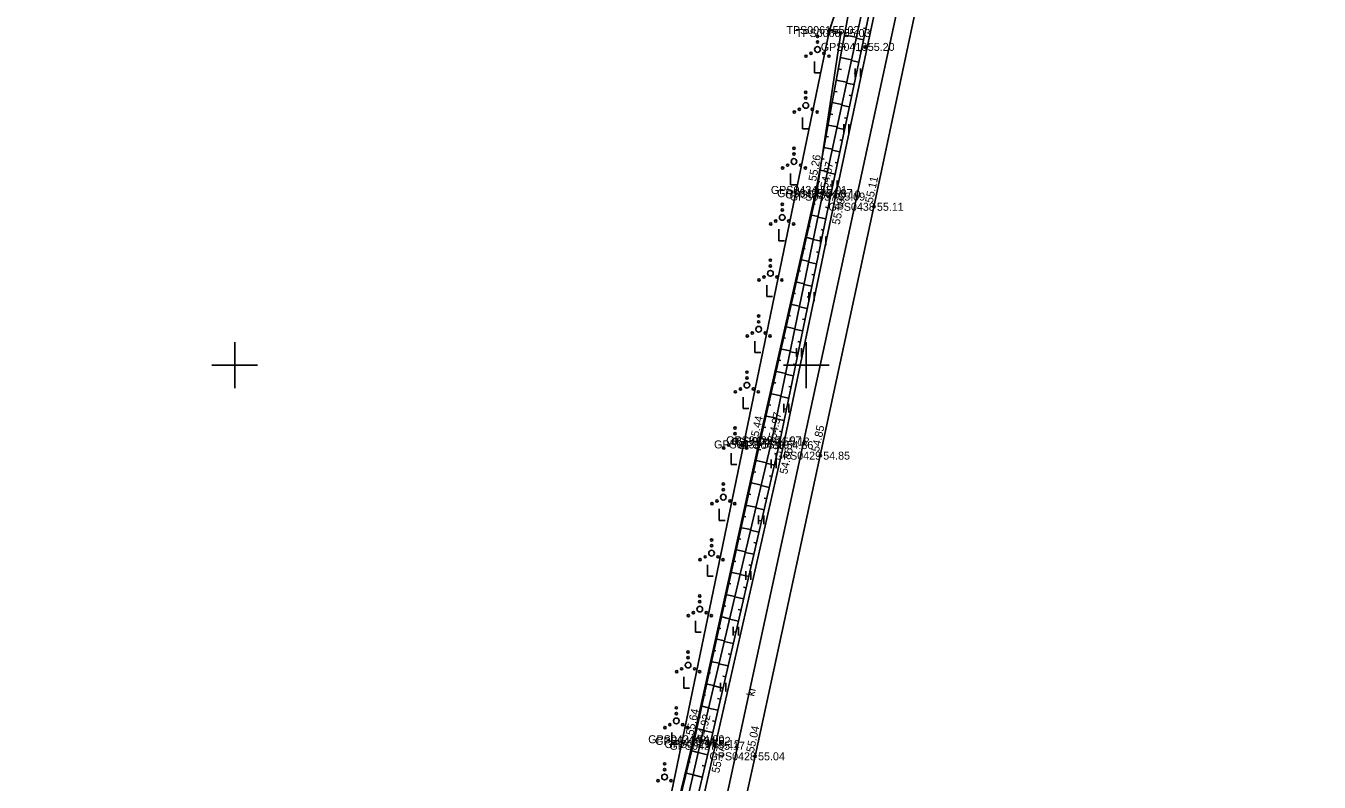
# Model space of a CAD drawing. Extents: x 551623 to 559850, y 6561220 to 6567135.
# Drawn here: x 556681.7 to 556794.9, y 6563363.5 to 6563429.7 of the extents above; entities that cross this region are included whole.
import ezdxf

# ---------------------------------------------------------------- set-up
doc = ezdxf.new("R2010")
doc.units = 0
for name, color, linetype in [('HALJASTUS', 7, 'Continuous'), ('KORGUS-EH2000', 7, 'Continuous'), ('MOOTKORG-EH2000', 7, 'Continuous'), ('MOOTMPUNKT', 7, 'Continuous'), ('MOOTNR', 7, 'Continuous'), ('MOOTPIIR', 7, 'Continuous'), ('PIIR', 7, 'Continuous'), ('RELJEEF', 7, 'Continuous'), ('TEE', 7, 'Continuous'), ('VORK', 7, 'Continuous')]:
    doc.layers.add(name, color=color, linetype=linetype)

msp = doc.modelspace()

# ---------------------------------------------------------------- linework, layer by layer
at = {"layer": 'HALJASTUS'}
for p, q in [((556750.72, 6563426.55), (556750.72, 6563425.55)), ((556750.72, 6563425.55), (556751.22, 6563425.55)), ((556754.29, 6563425.95), (556754.29, 6563425.19)), ((556754.75, 6563425.95), (556754.75, 6563425.19)), ((556749.68, 6563421.66), (556749.68, 6563420.66)), ((556753.28, 6563421.06), (556753.28, 6563420.29)), ((556753.73, 6563421.06), (556753.73, 6563420.29)), ((556749.68, 6563420.66), (556750.18, 6563420.66)), ((556748.64, 6563416.77), (556748.64, 6563415.77)), ((556748.64, 6563415.77), (556749.14, 6563415.77)), ((556752.26, 6563416.16), (556752.26, 6563415.4)), ((556752.72, 6563416.16), (556752.72, 6563415.4)), ((556747.6, 6563411.88), (556747.6, 6563410.88)), ((556747.6, 6563410.88), (556748.1, 6563410.88)), ((556751.25, 6563411.26), (556751.25, 6563410.5)), ((556751.71, 6563411.26), (556751.71, 6563410.5)), ((556746.56, 6563406.99), (556746.56, 6563405.99)), ((556750.24, 6563406.37), (556750.24, 6563405.61)), ((556750.69, 6563406.37), (556750.69, 6563405.61)), ((556746.56, 6563405.99), (556747.06, 6563405.99)), ((556745.52, 6563402.1), (556745.52, 6563401.1)), ((556745.52, 6563401.1), (556746.02, 6563401.1)), ((556749.14, 6563401.49), (556749.14, 6563400.73)), ((556749.59, 6563401.49), (556749.59, 6563400.73)), ((556744.48, 6563397.21), (556744.48, 6563396.21)), ((556744.48, 6563396.21), (556744.98, 6563396.21)), ((556748.03, 6563396.61), (556748.03, 6563395.85)), ((556748.49, 6563396.61), (556748.49, 6563395.85)), ((556743.44, 6563392.32), (556743.44, 6563391.32)), ((556746.93, 6563391.74), (556746.93, 6563390.98)), ((556747.38, 6563391.74), (556747.38, 6563390.98)), ((556743.44, 6563391.32), (556743.94, 6563391.32)), ((556742.4, 6563387.43), (556742.4, 6563386.43)), ((556742.4, 6563386.43), (556742.9, 6563386.43)), ((556745.82, 6563386.86), (556745.82, 6563386.1)), ((556746.28, 6563386.86), (556746.28, 6563386.1)), ((556741.36, 6563382.54), (556741.36, 6563381.54)), ((556741.36, 6563381.54), (556741.86, 6563381.54)), ((556744.72, 6563381.98), (556744.72, 6563381.22)), ((556745.17, 6563381.98), (556745.17, 6563381.22)), ((556740.32, 6563377.65), (556740.32, 6563376.65)), ((556743.62, 6563377.11), (556743.62, 6563376.35)), ((556744.07, 6563377.11), (556744.07, 6563376.35)), ((556740.32, 6563376.65), (556740.82, 6563376.65)), ((556739.28, 6563372.76), (556739.28, 6563371.76)), ((556742.51, 6563372.23), (556742.51, 6563371.47)), ((556742.97, 6563372.23), (556742.97, 6563371.47)), ((556739.28, 6563371.76), (556739.78, 6563371.76)), ((556738.24, 6563367.87), (556738.24, 6563366.87)), ((556738.24, 6563366.87), (556738.74, 6563366.87)), ((556741.41, 6563367.35), (556741.41, 6563366.59)), ((556741.86, 6563367.35), (556741.86, 6563366.59))]:
    msp.add_line(p, q, dxfattribs=at)
msp.add_lwpolyline([(556752.05, 6563429.3), (556753.02, 6563429.04), (556750.97, 6563415.32), (556745.92, 6563393.07), (556740.24, 6563367.29), (556734.99, 6563345.72), (556730.18, 6563321.97), (556724.64, 6563294.5)], dxfattribs=at)
for centre, radius in [((556750.99, 6563428.75), 0.1), ((556750.99, 6563427.6), 0.25), ((556750.99, 6563428.25), 0.1), ((556749.99, 6563427.02), 0.1), ((556750.42, 6563427.27), 0.1), ((556751.55, 6563427.27), 0.1), ((556751.99, 6563427.02), 0.1), ((556749.96, 6563423.86), 0.1), ((556749.96, 6563423.36), 0.1), ((556748.96, 6563422.13), 0.1), ((556749.4, 6563422.38), 0.1), ((556749.96, 6563422.71), 0.25), ((556750.53, 6563422.38), 0.1), ((556750.96, 6563422.13), 0.1), ((556748.93, 6563418.96), 0.1), ((556748.37, 6563417.49), 0.1), ((556748.93, 6563417.81), 0.25), ((556748.93, 6563418.46), 0.1), ((556749.5, 6563417.49), 0.1), ((556747.93, 6563417.24), 0.1), ((556749.93, 6563417.24), 0.1), ((556747.9, 6563414.07), 0.1), ((556747.9, 6563412.92), 0.25), ((556747.9, 6563413.57), 0.1), ((556746.9, 6563412.35), 0.1), ((556747.34, 6563412.6), 0.1), ((556748.47, 6563412.6), 0.1), ((556748.9, 6563412.35), 0.1), ((556746.87, 6563409.18), 0.1), ((556746.87, 6563408.68), 0.1), ((556745.87, 6563407.45), 0.1), ((556746.31, 6563407.7), 0.1), ((556746.87, 6563408.03), 0.25), ((556747.44, 6563407.7), 0.1), ((556747.87, 6563407.45), 0.1), ((556745.84, 6563404.29), 0.1), ((556745.84, 6563403.79), 0.1), ((556745.28, 6563402.81), 0.1), ((556745.84, 6563403.14), 0.25), ((556746.41, 6563402.81), 0.1), ((556744.84, 6563402.56), 0.1), ((556746.84, 6563402.56), 0.1), ((556744.81, 6563399.39), 0.1), ((556744.81, 6563398.24), 0.25), ((556744.81, 6563398.89), 0.1), ((556743.81, 6563397.67), 0.1), ((556744.25, 6563397.92), 0.1), ((556745.38, 6563397.92), 0.1), ((556745.81, 6563397.67), 0.1), ((556743.78, 6563394.5), 0.1), ((556743.78, 6563394), 0.1), ((556742.78, 6563392.77), 0.1), ((556743.22, 6563393.02), 0.1), ((556743.78, 6563393.35), 0.25), ((556744.35, 6563393.02), 0.1), ((556744.78, 6563392.77), 0.1), ((556742.75, 6563389.61), 0.1), ((556742.75, 6563389.11), 0.1), ((556742.19, 6563388.13), 0.1), ((556742.75, 6563388.46), 0.25), ((556743.32, 6563388.13), 0.1), ((556741.75, 6563387.88), 0.1), ((556743.75, 6563387.88), 0.1), ((556741.72, 6563384.71), 0.1), ((556741.72, 6563383.56), 0.25), ((556741.72, 6563384.21), 0.1), ((556740.72, 6563382.99), 0.1), ((556741.16, 6563383.24), 0.1), ((556742.29, 6563383.24), 0.1), ((556742.72, 6563382.99), 0.1), ((556740.69, 6563379.82), 0.1), ((556740.69, 6563379.32), 0.1), ((556739.69, 6563378.1), 0.1), ((556740.13, 6563378.35), 0.1), ((556740.69, 6563378.67), 0.25), ((556741.26, 6563378.35), 0.1), ((556741.69, 6563378.1), 0.1), ((556739.67, 6563374.93), 0.1), ((556739.67, 6563374.43), 0.1), ((556739.1, 6563373.45), 0.1), ((556739.67, 6563373.78), 0.25), ((556740.23, 6563373.45), 0.1), ((556738.67, 6563373.2), 0.1), ((556740.67, 6563373.2), 0.1), ((556738.64, 6563370.04), 0.1), ((556738.64, 6563368.89), 0.25), ((556738.64, 6563369.54), 0.1), ((556737.64, 6563368.31), 0.1), ((556738.07, 6563368.56), 0.1), ((556739.2, 6563368.56), 0.1), ((556739.64, 6563368.31), 0.1), ((556737.61, 6563365.14), 0.1), ((556737.61, 6563364.64), 0.1), ((556737.04, 6563363.67), 0.1), ((556737.61, 6563363.99), 0.25), ((556738.17, 6563363.67), 0.1)]:
    msp.add_circle(centre, radius, dxfattribs=at)
at = {"layer": 'KORGUS-EH2000'}
for centre in [(556752.05, 6563429.3), (556750.87, 6563415.32), (556751.45, 6563415.04), (556752.55, 6563414.74), (556755.93, 6563413.85), (556745.82, 6563393.07), (556746.99, 6563393.43), (556748.02, 6563393.01), (556751.23, 6563392.09), (556740.14, 6563367.29), (556740.78, 6563367.15), (556742.03, 6563366.72), (556745.53, 6563365.8)]:
    msp.add_circle(centre, 0.1, dxfattribs=at)
at = {"layer": 'MOOTMPUNKT'}
for centre in [(556752.05, 6563429.3), (556753.02, 6563429.04), (556755.13, 6563427.83), (556750.97, 6563415.32), (556751.45, 6563415.04), (556752.15, 6563414.93), (556752.55, 6563414.74), (556755.93, 6563413.85), (556745.92, 6563393.07), (556746.99, 6563393.43), (556747.69, 6563393.32), (556748.02, 6563393.01), (556751.23, 6563392.09), (556740.24, 6563367.29), (556740.78, 6563367.15), (556741.59, 6563366.87), (556742.03, 6563366.72), (556745.53, 6563365.8)]:
    msp.add_circle(centre, 0.1, dxfattribs=at)
at = {"layer": 'MOOTPIIR'}
for points in [[(556838.11, 6563834.55), (556835.41, 6563819.71), (556832.84, 6563805.21), (556829.97, 6563791.05), (556817.02, 6563726.91), (556811.4, 6563702.98), (556809.87, 6563694.7), (556802.57, 6563656), (556787.2, 6563585.15), (556769.06, 6563503.89), (556765.06, 6563485.61), (556759.97, 6563461.04), (556756.48, 6563442.49), (556752.05, 6563429.3), (556734.71, 6563345.75), (556730.03, 6563322.01), (556724.17, 6563296.08)], [(556729.29, 6563292.9), (556735.48, 6563320.27), (556740.75, 6563344.33), (556745.53, 6563365.8), (556751.23, 6563392.09), (556755.93, 6563413.85), (556759.83, 6563432.26), (556765.34, 6563459.93), (556770.39, 6563483.2), (556774.26, 6563501.22), (556779.1, 6563523.16), (556783.96, 6563544), (556788.05, 6563560.08), (556792.78, 6563582.54)]]:
    msp.add_lwpolyline(points, dxfattribs=at)
at = {"layer": 'PIIR'}
for points in [[(556692.98, 6563093.02), (556685.3, 6563096.1), (556759.6, 6563438.6), (556879.9, 6563970.48), (556916.82, 6563976.19), (557019.97, 6563895.21), (557017.46, 6563837.28), (557005.87, 6563342.24), (557215.7, 6563357.7), (557240.89, 6563286.87), (557262.52, 6563223.53), (557224.32, 6563129.01), (557161.59, 6562973.57), (557123.42, 6562995.07), (557058.18, 6562998.97)], [(555805.16, 6562850.3), (555826.95, 6563063.64), (555846.51, 6563164.12), (555894.51, 6563325.36), (556136, 6563572.22), (556237.49, 6563672.14), (556288.75, 6563676.33), (556560.07, 6563698.51), (556620.28, 6563801.97), (556702.51, 6563943.25), (556780.4, 6563955.1), (556879.9, 6563970.48), (556759.6, 6563438.6), (556685.3, 6563096.1), (556692.98, 6563093.02), (556667.97, 6562987.78), (556646.18, 6562894.39), (556231.34, 6562873.47), (556132.45, 6562866.66), (555973.8, 6562858.59)]]:
    msp.add_lwpolyline(points, close=True, dxfattribs=at)
at = {"layer": 'RELJEEF'}
for p, q in [((556753.34, 6563428.86), (556754.39, 6563428.67)), ((556755.21, 6563429.43), (556755.02, 6563429.47)), ((556753.16, 6563427.87), (556753.47, 6563427.82)), ((556755.01, 6563428.45), (556754.37, 6563428.58)), ((556752.98, 6563426.89), (556753.96, 6563426.71)), ((556754.59, 6563426.49), (556753.95, 6563426.63)), ((556754.8, 6563427.47), (556754.61, 6563427.51)), ((556752.8, 6563425.91), (556753.09, 6563425.85)), ((556754.39, 6563425.51), (556754.19, 6563425.55)), ((556752.62, 6563424.92), (556753.54, 6563424.76)), ((556754.18, 6563424.53), (556753.52, 6563424.67)), ((556752.45, 6563423.94), (556752.71, 6563423.89)), ((556753.97, 6563423.56), (556753.77, 6563423.6)), ((556752.27, 6563422.96), (556753.12, 6563422.8)), ((556753.77, 6563422.58), (556753.1, 6563422.72)), ((556751.91, 6563420.99), (556752.7, 6563420.84)), ((556752.09, 6563421.97), (556752.33, 6563421.93)), ((556753.56, 6563421.6), (556753.36, 6563421.64)), ((556751.73, 6563420), (556751.95, 6563419.96)), ((556753.35, 6563420.62), (556752.68, 6563420.76)), ((556751.55, 6563419.02), (556752.28, 6563418.89)), ((556752.94, 6563418.66), (556752.26, 6563418.81)), ((556753.14, 6563419.64), (556752.94, 6563419.69)), ((556751.37, 6563418.04), (556751.58, 6563418)), ((556752.73, 6563417.69), (556752.53, 6563417.73)), ((556751.19, 6563417.05), (556751.86, 6563416.93)), ((556752.52, 6563416.71), (556751.84, 6563416.85)), ((556751.01, 6563416.07), (556751.2, 6563416.03)), ((556752.32, 6563415.73), (556752.11, 6563415.77)), ((556750.6, 6563414.11), (556750.79, 6563414.07)), ((556750.82, 6563415.09), (556751.43, 6563414.95)), ((556752.11, 6563414.75), (556751.42, 6563414.89)), ((556750.38, 6563413.14), (556751.02, 6563412.99)), ((556751.71, 6563412.79), (556751.01, 6563412.93)), ((556751.91, 6563413.77), (556751.7, 6563413.81)), ((556750.15, 6563412.16), (556750.35, 6563412.12)), ((556751.5, 6563411.81), (556751.3, 6563411.86)), ((556749.93, 6563411.19), (556750.62, 6563411.03)), ((556751.3, 6563410.83), (556750.61, 6563410.98)), ((556749.71, 6563410.21), (556749.92, 6563410.16)), ((556751.1, 6563409.85), (556750.89, 6563409.9)), ((556749.49, 6563409.24), (556750.22, 6563409.07)), ((556750.9, 6563408.87), (556750.2, 6563409.02)), ((556749.05, 6563407.29), (556749.81, 6563407.11)), ((556749.27, 6563408.26), (556749.49, 6563408.21)), ((556750.7, 6563407.9), (556750.49, 6563407.94)), ((556748.83, 6563406.31), (556749.06, 6563406.26)), ((556750.49, 6563406.92), (556749.8, 6563407.06)), ((556748.61, 6563405.34), (556749.41, 6563405.15)), ((556750.09, 6563404.96), (556749.4, 6563405.1)), ((556750.29, 6563405.94), (556750.08, 6563405.98)), ((556748.39, 6563404.36), (556748.63, 6563404.3)), ((556749.89, 6563403.98), (556749.68, 6563404.02)), ((556748.16, 6563403.38), (556749, 6563403.19)), ((556749.69, 6563403), (556748.99, 6563403.14)), ((556747.94, 6563402.41), (556748.2, 6563402.35)), ((556749.48, 6563402.02), (556749.28, 6563402.06)), ((556747.72, 6563401.43), (556748.6, 6563401.24)), ((556749.28, 6563401.04), (556748.59, 6563401.18)), ((556747.28, 6563399.48), (556748.19, 6563399.28)), ((556747.5, 6563400.46), (556747.77, 6563400.4)), ((556749.08, 6563400.06), (556748.87, 6563400.1)), ((556747.06, 6563398.51), (556747.34, 6563398.44)), ((556748.88, 6563399.08), (556748.18, 6563399.22)), ((556746.84, 6563397.53), (556747.79, 6563397.32)), ((556748.48, 6563397.12), (556747.78, 6563397.27)), ((556748.68, 6563398.1), (556748.47, 6563398.14)), ((556746.62, 6563396.56), (556746.91, 6563396.49)), ((556748.27, 6563396.14), (556748.06, 6563396.19)), ((556746.4, 6563395.58), (556747.38, 6563395.36)), ((556748.07, 6563395.16), (556747.37, 6563395.31)), ((556746.17, 6563394.61), (556746.48, 6563394.54)), ((556747.87, 6563394.18), (556747.66, 6563394.23)), ((556745.73, 6563392.66), (556746.04, 6563392.59)), ((556745.95, 6563393.63), (556746.98, 6563393.4)), ((556747.66, 6563393.2), (556746.97, 6563393.36)), ((556745.52, 6563391.68), (556746.52, 6563391.46)), ((556747.44, 6563392.23), (556747.23, 6563392.28)), ((556745.3, 6563390.7), (556745.6, 6563390.64)), ((556747.22, 6563391.26), (556746.51, 6563391.42)), ((556746.99, 6563390.28), (556746.78, 6563390.33)), ((556745.09, 6563389.73), (556746.06, 6563389.51)), ((556746.77, 6563389.31), (556746.05, 6563389.47)), ((556744.87, 6563388.75), (556745.16, 6563388.69)), ((556746.54, 6563388.33), (556746.33, 6563388.38)), ((556744.66, 6563387.77), (556745.6, 6563387.57)), ((556746.32, 6563387.36), (556745.59, 6563387.53)), ((556744.23, 6563385.82), (556745.14, 6563385.62)), ((556744.44, 6563386.8), (556744.72, 6563386.74)), ((556746.09, 6563386.38), (556745.87, 6563386.43)), ((556744.01, 6563384.84), (556744.28, 6563384.78)), ((556745.87, 6563385.41), (556745.13, 6563385.58)), ((556743.79, 6563383.87), (556744.68, 6563383.67)), ((556745.42, 6563383.46), (556744.67, 6563383.63)), ((556745.64, 6563384.43), (556745.42, 6563384.49)), ((556743.58, 6563382.89), (556743.84, 6563382.83)), ((556745.19, 6563382.49), (556744.97, 6563382.54)), ((556743.36, 6563381.91), (556744.22, 6563381.73)), ((556744.97, 6563381.51), (556744.21, 6563381.69)), ((556743.15, 6563380.94), (556743.4, 6563380.88)), ((556744.74, 6563380.54), (556744.52, 6563380.59)), ((556742.93, 6563379.96), (556743.76, 6563379.78)), ((556744.52, 6563379.56), (556743.75, 6563379.74)), ((556742.5, 6563378.01), (556743.3, 6563377.83)), ((556742.72, 6563378.99), (556742.96, 6563378.93)), ((556744.3, 6563378.59), (556744.06, 6563378.64)), ((556742.29, 6563377.03), (556742.52, 6563376.98)), ((556744.07, 6563377.61), (556743.29, 6563377.79)), ((556742.07, 6563376.06), (556742.84, 6563375.89)), ((556743.62, 6563375.66), (556742.83, 6563375.85)), ((556743.85, 6563376.64), (556743.61, 6563376.69)), ((556741.85, 6563375.08), (556742.08, 6563375.03)), ((556743.4, 6563374.69), (556743.16, 6563374.75)), ((556741.64, 6563374.1), (556742.38, 6563373.94)), ((556743.17, 6563373.72), (556742.37, 6563373.9)), ((556741.42, 6563373.13), (556741.64, 6563373.08)), ((556742.95, 6563372.74), (556742.71, 6563372.8)), ((556740.99, 6563371.17), (556741.2, 6563371.13)), ((556741.21, 6563372.15), (556741.92, 6563371.99)), ((556742.72, 6563371.77), (556741.91, 6563371.95)), ((556740.78, 6563370.2), (556741.46, 6563370.05)), ((556742.27, 6563369.82), (556741.45, 6563370.01)), ((556742.5, 6563370.79), (556742.25, 6563370.85)), ((556740.56, 6563369.22), (556740.76, 6563369.18)), ((556742.05, 6563368.84), (556741.8, 6563368.9)), ((556740.35, 6563368.24), (556741, 6563368.1)), ((556741.82, 6563367.87), (556740.99, 6563368.06)), ((556741.6, 6563366.89), (556741.35, 6563366.95)), ((556739.89, 6563366.3), (556740.55, 6563366.14)), ((556741.37, 6563365.92), (556740.54, 6563366.12)), ((556739.42, 6563364.35), (556740.1, 6563364.19)), ((556739.66, 6563365.32), (556739.86, 6563365.28)), ((556741.14, 6563364.95), (556740.89, 6563365.01)), ((556740.91, 6563363.98), (556740.1, 6563364.17))]:
    msp.add_line(p, q, dxfattribs=at)
for points in [[(556788.59, 6563584.23), (556783.65, 6563561.56), (556779.99, 6563544.9), (556774.7, 6563524.07), (556769.69, 6563502.72), (556765.66, 6563484.53), (556760.96, 6563460.73), (556757.31, 6563442.67), (556755.33, 6563433.04), (556751.45, 6563415.04), (556746.99, 6563393.43), (556740.78, 6563367.15), (556735.87, 6563345.63), (556730.71, 6563320.48)], [(556755.97, 6563432.99), (556752.15, 6563414.93), (556747.69, 6563393.32), (556741.59, 6563366.87), (556736.55, 6563345.62), (556731.66, 6563321.22), (556730.71, 6563320.48), (556730.03, 6563322.01), (556734.89, 6563345.72), (556740.14, 6563367.29), (556745.82, 6563393.07), (556750.87, 6563415.32), (556754.08, 6563432.88)]]:
    msp.add_lwpolyline(points, dxfattribs=at)
at = {"layer": 'TEE'}
for points in [[(556789.65, 6563583.8), (556784.53, 6563561.18), (556780.77, 6563544.63), (556775.84, 6563524.15), (556770.72, 6563502.37), (556766.84, 6563484.07), (556762.2, 6563460.74), (556758.47, 6563442.44), (556756.4, 6563432.89), (556752.55, 6563414.74), (556748.02, 6563393.01), (556742.03, 6563366.72), (556737.2, 6563345.43), (556731.92, 6563321.06), (556725.97, 6563293.68)], [(556792.78, 6563582.54), (556788.05, 6563560.08), (556783.96, 6563544), (556779.1, 6563523.16), (556774.26, 6563501.22), (556770.39, 6563483.2), (556765.34, 6563459.93), (556761.87, 6563441.55), (556759.83, 6563432.26), (556755.93, 6563413.85), (556751.23, 6563392.09), (556745.53, 6563365.8), (556740.75, 6563344.33), (556735.48, 6563320.27), (556729.29, 6563292.9)]]:
    msp.add_lwpolyline(points, dxfattribs=at)
at = {"layer": 'VORK'}
for p, q in [((556700, 6563402), (556700, 6563398)), ((556750, 6563402), (556750, 6563398)), ((556698, 6563400), (556702, 6563400)), ((556748, 6563400), (556752, 6563400))]:
    msp.add_line(p, q, dxfattribs=at)

# ---------------------------------------------------------------- texts
at = {"layer": 'KORGUS-EH2000'}
for s, rotation, p in [('55.26', 79.6434, (556750.87, 6563416.04)), (' 54.87', 77.8368, (556751.84, 6563415.16)), (' 55.11', 78.0584, (556755.76, 6563413.88)), (' 55.09', 78.2101, (556752.87, 6563411.99)), ('55.44', 77.2252, (556745.71, 6563393.19)), (' 54.97', 78.3313, (556747.32, 6563393.27)), (' 54.85', 77.7959, (556751.06, 6563392.12)), (' 54.86', 77.1699, (556748.27, 6563390.17)), ('55.64', 77.5535, (556740.13, 6563367.59)), (' 54.92', 76.7131, (556741.04, 6563366.86)), (' 55.04', 77.7727, (556745.36, 6563365.84)), (' 55.17', 77.2262, (556742.32, 6563364.03))]:
    msp.add_text(s, height=0.7, rotation=rotation, dxfattribs=at).set_placement(p)
at = {"layer": 'MOOTKORG-EH2000'}
for s, p in [(' 55.02', (556752.05, 6563428.95)), (' 55.03', (556753.02, 6563428.69)), (' 55.20', (556755.13, 6563427.48)), (' 55.01', (556750.97, 6563414.97)), (' 54.87', (556751.45, 6563414.69)), (' 55.10', (556752.15, 6563414.58)), (' 55.09', (556752.55, 6563414.39)), (' 55.11', (556755.93, 6563413.5)), (' 54.97', (556746.99, 6563393.08)), (' 55.19', (556745.92, 6563392.72)), (' 55.18', (556747.69, 6563392.97)), (' 54.86', (556748.02, 6563392.66)), (' 54.85', (556751.23, 6563391.74)), (' 54.90', (556740.24, 6563366.94)), (' 54.92', (556740.78, 6563366.8)), (' 55.12', (556741.59, 6563366.52)), (' 55.17', (556742.03, 6563366.37)), (' 55.04', (556745.53, 6563365.45))]:
    msp.add_text(s, height=0.7, dxfattribs=at).set_placement(p)
at = {"layer": 'MOOTNR'}
for s, p in [('TPS0061 ', (556748.27, 6563428.95)), ('TPS0060 ', (556749.1, 6563428.69)), ('GPS0410 ', (556751.28, 6563427.48)), ('GPS0434 ', (556746.91, 6563414.97)), ('GPS0435 ', (556747.46, 6563414.69)), ('GPS0436 ', (556748.16, 6563414.58)), ('GPS0437 ', (556748.56, 6563414.39)), ('GPS0438 ', (556751.94, 6563413.5)), ('GPS0432 ', (556743, 6563393.08)), ('GPS0433 ', (556741.94, 6563392.72)), ('GPS0431 ', (556743.84, 6563392.97)), ('GPS0430 ', (556744.03, 6563392.66)), ('GPS0429 ', (556747.24, 6563391.74)), ('GPS0424 ', (556736.18, 6563366.94)), ('GPS0425 ', (556736.79, 6563366.8)), ('GPS0426 ', (556737.6, 6563366.52)), ('GPS0427 ', (556738.04, 6563366.37)), ('GPS0428 ', (556741.54, 6563365.45))]:
    msp.add_text(s, height=0.7, dxfattribs=at).set_placement(p)
at = {"layer": 'TEE'}
msp.add_text('kr', height=0.7, rotation=77.4567, dxfattribs=at).set_placement((556745.45, 6563371))

doc.saveas('drawing.dxf')
